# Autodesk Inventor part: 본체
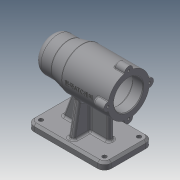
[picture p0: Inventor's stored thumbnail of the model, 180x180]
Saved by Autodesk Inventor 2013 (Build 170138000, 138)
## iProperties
Created: 2019-07
Part Number: 본체
Material: Generic
Document SubType Name: Modeling
Designer: user
Density: 1 g/cm^3
Author: user
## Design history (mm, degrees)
sketch "스케치1"
  geometry: L1 (0, 0)-(0, 112); L2 (0, 112)-(25, 112); L3 (25, 112)-(25, 87); L4 (25, 87)-(30, 67); L5 (30, 67)-(30, 0); L6 (30, 0)-(0, 0); 1 further point
  constraints: 12 end point, 2 parallel, 2 perpendicular, 1 coincident, 1 vertical
  dimensions: "d0" = 112 distance of L1.start L1.end; "d1" = 50 diameter of L3 L1; "d2" = 60 diameter of L5 L1; "d3" = 25 distance from line of L2 L3.end; "d4" = 45 distance from line of L2 L4.end
revolve "회전1" sketch "스케치1" stored, may be unused: angle "d5" = 90 deg
fillet "모깎기1" dims "d6" = 10
sketch "스케치2"
  geometry: L1 (-15, 112)-(15, 112) reference; L2 (0, 0)-(0, 112); L3 (0, 0)-(21, 0); L4 (21, 0)-(21, 15); L5 (21, 15)-(24, 15); L6 (24, 15)-(24, 69); L7 (24, 69)-(21, 69); L8 (21, 69)-(21, 81); L9 (21, 81)-(17.5, 81); L10 (17.5, 81)-(17.5, 99); L11 (17.5, 99)-(16, 99); L12 (16, 99)-(16, 103); L13 (16, 103)-(10.5, 103); L14 (10.5, 103)-(10.5, 106); L15 (10.5, 106)-(0, 106)
  constraints: 28 end point, 9 parallel, 3 perpendicular, 1 collinear, 1 midpoint, 1 point on line
  dimensions: "d7" = 42 diameter of L4 L2; "d9" = 48 diameter of L6 L2; "d10" = 42 diameter of L8 L2; "d11" = 35 diameter of L10 L2; "d12" = 32 diameter of L12 L2; "d13" = 21 diameter of L14 L2; "d14" = 15 distance from line of L2.start L5; "d15" = 54 distance of L5.end L6.end; "d16" = 12 distance of L7.end L8.end; "d17" = 18 distance of L9.end L10.end; "d18" = 4 distance of L11.end L12.end; "d19" = 3 distance of L13.end L14.end
revolve "회전2" sketch "스케치2" stored, may be unused: angle "d20" = 90 deg
fillet "모깎기9" dims "d79" = 3
node "작업 평면1"
sketch "스케치3"
  geometry: L1 (-30, 0)-(30, 0) reference; L2 (35, 0)-(-35, 0); L3 (-35, 0)-(-35, 112); L4 (-35, 112)-(35, 112); L5 (35, 112)-(35, 0); 2 further points
  constraints: 8 end point, 2 midpoint, 2 parallel, 1 horizontal, 1 perpendicular
  dimensions: "d22" = 70 distance of L3.end L4.end; "d23" = 112 distance of L2.end L3.end
extrude "돌출1" join sketch "스케치3" distance "d24" = 10; taper "d25" = 0 deg
node "작업 평면2"
sketch "스케치4"
  geometry: L1 (35, -70)-(35, -80) reference; L2 (35, -80)-(-35, -80) reference; L3 (-35, -80)-(-35, -70) reference; L4 (-35, -70)-(35, -70) reference; L5 (-28, -70)-(-19.654, -22.666); L6 (19.654, -22.666)-(28, -70); C1 r 24 at (0, 0) reference; A1 r 30 centre (0, 0) between (-19.654, -22.666) and (19.654, -22.666) reference; 1 further point
  constraints: 4 end point, 2 point on circle, 2 point on line
  dimensions: "d27" = 7 distance from line of L3 L5.start; "d28" = 7 distance from line of L1 L6.end; "d29" = 100 deg angle of L4 L6; "d30" = 100 deg angle of L4 L5
extrude "돌출2" join sketch "스케치4" stored distance "d31" = 8; taper "d32" = 0 deg
sketch "스케치5"
  geometry: L1 (25, 102)-(25, 87) reference; L2 (25, 87)-(29.91, 67.358) reference; L3 (30, 66.631)-(30, 0) reference; L4 (30, 0)-(21, 0) reference; L5 (21, 0)-(21, 15) reference; L6 (21, 15)-(24, 15) reference; L7 (24, 15)-(24, 69) reference; L8 (24, 69)-(21, 69) reference; L9 (21, 69)-(21, 81) reference; L10 (21, 81)-(17.5, 81) reference; L11 (17.5, 81)-(17.5, 99) reference; L12 (17.5, 99)-(16, 99) reference; L13 (16, 99)-(16, 103) reference; L14 (16, 103)-(10.5, 103) reference; L15 (10.5, 103)-(10.5, 106) reference; L16 (10.5, 106)-(-10.5, 106) reference; L17 (-10.5, 106)-(-10.5, 103) reference; L18 (-10.5, 103)-(-16, 103) reference; L19 (-16, 103)-(-16, 99) reference; L20 (-16, 99)-(-17.5, 99) reference; L21 (-17.5, 99)-(-17.5, 81) reference; L22 (-17.5, 81)-(-21, 81) reference; L23 (-21, 81)-(-21, 69) reference; L24 (-21, 69)-(-24, 69) reference; L25 (-24, 69)-(-24, 15) reference; L26 (-24, 15)-(-21, 15) reference; L27 (-21, 15)-(-21, 0) reference; L28 (-21, 0)-(-30, 0) reference; L29 (-30, 0)-(-30, 52) reference; L30 (-30, 52)-(-70, 52) reference; L31 (-70, 52)-(-70, 0) reference; L32 (-70, 0)-(-80, 0) reference; L33 (-80, 0)-(-80, 112) reference; L34 (-80, 112)-(-70, 112) reference; L35 (-70, 112)-(-70, 60) reference; L36 (-70, 60)-(-30, 60) reference; L37 (-30, 60)-(-30, 66.631) reference; L38 (-29.91, 67.358)-(-25, 87) reference; L39 (-25, 87)-(-25, 102) reference; L40 (-15, 112)-(15, 112) reference; L41 (-27.607, 76.57)-(-70, 92); A1 r 10 centre (15, 102) between (25, 102) and (15, 112) reference; A2 r 10 centre (-15, 102) between (-15, 112) and (-25, 102) reference; A3 r 3 centre (27, 66.631) between (30, 66.631) and (29.91, 67.358) reference; A4 r 3 centre (-27, 66.631) between (-29.91, 67.358) and (-30, 66.631) reference; 1 further point
  constraints: 2 end point, 2 point on line
  dimensions: "d33" = 20 distance from line of L34 L41.end; "d34" = 110 deg angle of L35 L41
feature "리브1" sketch "스케치5" dims "d35" = 1, "d36" = 8, "d37" = 0, "d38" = 0, "d39" = 1, "d40" = 1
sketch "스케치6"
  geometry: L1 (25, 102)-(25, 87) reference; L2 (25, 87)-(29.91, 67.358) reference; L3 (30, 66.631)-(30, 0) reference; L4 (30, 0)-(21, 0) reference; L5 (21, 0)-(21, 15) reference; L6 (21, 15)-(24, 15) reference; L7 (24, 15)-(24, 69) reference; L8 (24, 69)-(21, 69) reference; L9 (21, 69)-(21, 81) reference; L10 (21, 81)-(17.5, 81) reference; L11 (17.5, 81)-(17.5, 99) reference; L12 (17.5, 99)-(16, 99) reference; L13 (16, 99)-(16, 103) reference; L14 (16, 103)-(10.5, 103) reference; L15 (10.5, 103)-(10.5, 106) reference; L16 (10.5, 106)-(-10.5, 106) reference; L17 (-10.5, 106)-(-10.5, 103) reference; L18 (-10.5, 103)-(-16, 103) reference; L19 (-16, 103)-(-16, 99) reference; L20 (-16, 99)-(-17.5, 99) reference; L21 (-17.5, 99)-(-17.5, 81) reference; L22 (-17.5, 81)-(-21, 81) reference; L23 (-21, 81)-(-21, 69) reference; L24 (-21, 69)-(-24, 69) reference; L25 (-24, 69)-(-24, 15) reference; L26 (-24, 15)-(-21, 15) reference; L27 (-21, 15)-(-21, 0) reference; L28 (-21, 0)-(-30, 0) reference; L29 (-30, 0)-(-30, 52) reference; L30 (-30, 52)-(-70, 52) reference; L31 (-70, 52)-(-70, 0) reference; L32 (-70, 0)-(-80, 0) reference; L33 (-80, 0)-(-80, 112) reference; L34 (-80, 112)-(-70, 112) reference; L35 (-70, 112)-(-70, 92) reference; L36 (-70, 92)-(-27.607, 76.57) reference; L37 (-27.607, 76.57)-(-25, 87) reference; L38 (-25, 87)-(-25, 102) reference; L39 (-15, 112)-(15, 112) reference; L40 (-30, 25)-(-70, 25); A1 r 10 centre (15, 102) between (25, 102) and (15, 112) reference; A2 r 10 centre (-15, 102) between (-15, 112) and (-25, 102) reference; A3 r 3 centre (27, 66.631) between (30, 66.631) and (29.91, 67.358) reference; 1 further point
  constraints: 2 end point, 2 point on line, 1 perpendicular
  dimensions: "d41" = 25 distance between parallel lines of L32 L40
feature "리브2" sketch "스케치6" dims "d42" = 1, "d43" = 8, "d44" = 0, "d45" = 0, "d46" = 1, "d47" = 1
sketch "스케치7"
  geometry: L1 (0, 0)-(0, 30); C1 r 30 at (0, 0) reference; C2 r 6 at (0, 30)
  constraints: 2 end point, 1 centre point, 1 coincident, 1 vertical
  dimensions: "d48" = 30 distance of L1.start L1.end; "d49" = 12 diameter of C2
extrude "돌출3" join sketch "스케치7" distance "d50" = 16; taper "d51" = 0 deg
sketch "스케치8"
  geometry: A1 r 6 centre (0, 0) between (5.97, -0.6) and (-5.97, -0.6) reference; 1 further point
  constraints: 1 coincident
hole "구멍1" sketch "스케치8" at (0, 0) diameter "d52" = 3.242; stored, may be unused: countersink angle "d56" = 90 deg, drill point angle "d58" = 118 deg; dims "d53" = 8, "d54" = 4, "d55" = 2, "d57" = 11
fillet "모깎기2" dims "d62" = 10
sketch "스케치9"
  geometry: A1 r 10 centre (-25, -102) between (-35, -102) and (-25, -112) reference; A2 r 10 centre (25, -102) between (25, -112) and (35, -102) reference; A3 r 10 centre (25, -10) between (35, -10) and (25, 0) reference; A4 r 10 centre (-25, -10) between (-25, 0) and (-35, -10) reference; 5 further points
  constraints: 4 coincident
hole "구멍2" sketch "스케치9" at (-25, -10), (-25, -102), (25, -102), (25, -10) diameter "d63" = 6; stored, may be unused: countersink angle "d67" = 90 deg, drill point angle "d69" = 118 deg; dims "d64" = 8, "d65" = 4, "d66" = 2, "d68" = 11
fillet "모깎기3" dims "d70" = 3
fillet "모깎기4" dims "d71" = 0.3
fillet "모깎기5" dims "d72" = 3
chamfer "모따기1" distance "d73" = 1; stored, may be unused: second distance "d74" = 2, angle "d75" = 45 deg
fillet "모깎기6" dims "d76" = 3
fillet "모깎기7" dims "d77" = 1
fillet "모깎기8" dims "d78" = 3
chamfer "모따기2" distance "d80" = 3; stored, may be unused: second distance "d81" = 2, angle "d82" = 45 deg
fillet "모깎기10" dims "d83" = 3
fillet "모깎기11" dims "d84" = 3
node "작업 평면3"
sketch "스케치10"
  geometry: 2 further points
  constraints: 1 vertical alignment, 1 other
  dimensions: "d86" = 42 distance of point (0, 0) point (0, 42)
feature "엠보싱1" sketch "스케치10" dims "d87" = 0.5, "d88" = 0
node "솔리드1"
pattern_circular "원형 패턴1" dims angle "d60" = 360 deg
node "절단 모서리 투영1"
node "절단 모서리 투영2"
node "절단 모서리 투영3"
other parameters: "d26" = 56
